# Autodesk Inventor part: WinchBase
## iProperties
Author: Administrator
Shininess: 20.0
PropertySet Name: _Private Model Information
Created: 2001-04
Part Number: WinchBase
Document SubType Name: Modeling
Designer: Administrator
Control State: 0
Master: False
Checked Out: False
PropertySet Name: Design Tracking Control
Density: 0.0
Volumn: 0.0
Area: 0.0
PropertySet Name: Model Information
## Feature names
1. Extrusion1
2. Extrusion2
